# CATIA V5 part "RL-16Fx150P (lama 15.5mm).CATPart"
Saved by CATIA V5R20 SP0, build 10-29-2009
Part number: _RL-16Fx150P (lama 15.5mm)
Definition: NONE
Nomenclature: _RL-16Fx150P (lama 15.5mm)
Source: Unknown
Description: PART-_RL-16Fx150P (lama 15.5mm)-DESC
Bounding box of the stored display mesh (mm): x -150 to 14, y -9 to 9, z -9 to 9
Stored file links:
  C:\Users\Utente\Desktop\IO LAVORO\3D X SITO CF\X SITO\PLASTICA\RLF\RL-16Fx150P (lama 15.5mm).CATPart
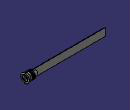
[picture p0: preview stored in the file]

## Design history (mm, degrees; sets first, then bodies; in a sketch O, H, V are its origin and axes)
Body1 "_RL-16Fx150P (lama 15.5mm)" (main body)
  Solid1: solid without history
